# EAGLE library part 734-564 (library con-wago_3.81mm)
Serie 734, Federleiste mit abgewinkelten Einlötstiften / Series 734, Female connector with angled solder pins Polzahl / Pole No.: 4 Bemessungsspannung / Rated Voltage: 160 V Nennstrom / Nominal Current: 10 A Lötstiftlänge: / Solder Pin Length: 3.8 mm Farbe / Color: orange / orange Stand: 01.01.2012. Die jeweils aktuellen Daten zu diesem Artikel finden Sie in unserem Produktkatalog, den Sie unter www.wago.com einsehen können. As of: 01/01/2012. Please find the newest data for this article in our product catalogue, which can be viewed under www.wago.com.
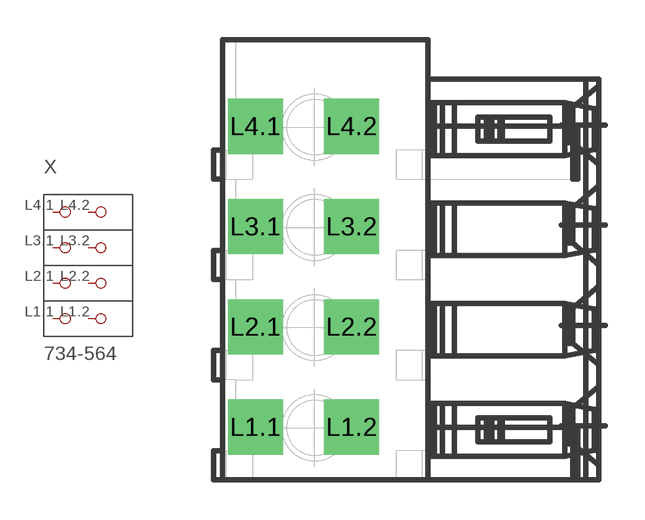
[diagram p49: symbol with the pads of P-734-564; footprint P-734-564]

Designator prefix X

## 734-564  [P-734-564]
L1.1  P1.1
L1.2  P1.2
L2.1  P2.1
L2.2  P2.2
L3.1  P3.1
L3.2  P3.2
L4.1  P4.1
L4.2  P4.2

## Footprint P-734-564 (pad centres in mm)
drill 1.4 square: L1.1 -5.845,-6.36; L1.2 -2.195,-6.36; L2.1 -5.845,-2.55; L2.2 -2.195,-2.55; L3.1 -5.845,1.26; L3.2 -2.195,1.26; L4.1 -5.845,5.07; L4.2 -2.195,5.07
